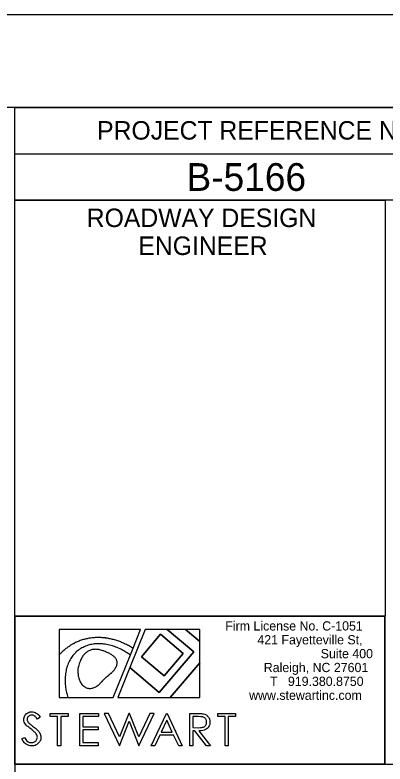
# Model space of a CAD drawing. Extents: x 1967100 to 1968800, y 964086 to 965186.
# Drawn here: x 1968574.5 to 1968674.5, y 964983.4 to 965186 of the extents above; entities that cross this region are included whole.
import ezdxf

# ---------------------------------------------------------------- set-up
doc = ezdxf.new("R2010")
doc.units = 0
for name, color, linetype in [('Sheet Data Field CELL', 7, 'Continuous'), ('Sheet Plan And Profile CELL', 7, 'Continuous'), ('Sheet Sticker Exception Certification CELL', 7, 'Continuous'), ('Stewart Logo', 7, 'Continuous'), ('Stewart Plot Border Xerox6279 and LJ5000', 7, 'Continuous')]:
    doc.layers.add(name, color=color, linetype=linetype)

msp = doc.modelspace()

# ---------------------------------------------------------------- linework, layer by layer
at = {"layer": 'Sheet Plan And Profile CELL'}
msp.add_line((1968574.47, 965148.43), (1968774.52, 965148.43), dxfattribs=at)
for points in [[(1968774.52, 965160.98), (1967274.52, 965160.98), (1967274.52, 964110.98), (1968774.52, 964110.98)], [(1968574.47, 965160.98), (1968774.52, 965160.98), (1968774.52, 965135.93), (1968574.47, 965135.93)], [(1968574.47, 965135.93), (1968674.52, 965135.93), (1968674.52, 965023.43), (1968574.47, 965023.43)], [(1968574.47, 965023.43), (1968674.47, 965023.43), (1968674.47, 964983.43), (1968574.47, 964983.43)]]:
    msp.add_lwpolyline(points, close=True, dxfattribs=at)
at = {"layer": 'Sheet Sticker Exception Certification CELL'}
for p, q in [((1968574.48, 964959.93), (1968574.48, 964983.43)), ((1968574.48, 964983.43), (1968774.52, 964983.43))]:
    msp.add_line(p, q, dxfattribs=at)
at = {"layer": 'Stewart Logo'}
for p, q in [((1968608.44, 965019.83), (1968586.37, 965019.83)), ((1968586.37, 965019.83), (1968586.37, 965012.88)), ((1968609.67, 965019.83), (1968605.52, 965009.51)), ((1968606.39, 965014.72), (1968608.44, 965019.83)), ((1968615.62, 965019.83), (1968609.67, 965019.83)), ((1968615.62, 965019.83), (1968622.77, 965013.74)), ((1968620.52, 965019.83), (1968615.62, 965019.83)), ((1968622.77, 965013.74), (1968615.62, 965019.83)), ((1968624.4, 965019.83), (1968620.52, 965019.83)), ((1968620.52, 965019.83), (1968624.4, 965016.52)), ((1968624.4, 965016.52), (1968620.52, 965019.83)), ((1968624.4, 965016.52), (1968624.4, 965019.83)), ((1968591.31, 965016.49), (1968591.29, 965016.46)), ((1968592.38, 965016.89), (1968592.33, 965016.88)), ((1968598.89, 965017.5), (1968598.9, 965017.5)), ((1968624.4, 965010.75), (1968624.4, 965016.52)), ((1968598.8, 965015.8), (1968598.84, 965015.82)), ((1968604.37, 965015.84), (1968604.38, 965015.84)), ((1968605.66, 965012.91), (1968606.39, 965014.72)), ((1968586.37, 965012.88), (1968586.37, 965001.42)), ((1968601.04, 965001.42), (1968605.66, 965012.91)), ((1968622.77, 965013.74), (1968613.44, 965002.77)), ((1968613.44, 965002.77), (1968622.77, 965013.74)), ((1968614.76, 965007.23), (1968619.94, 965013.32)), ((1968624.4, 965010.75), (1968616.46, 965001.42)), ((1968616.46, 965001.42), (1968624.4, 965010.75)), ((1968624.4, 965001.42), (1968624.4, 965010.75)), ((1968605.52, 965009.51), (1968602.27, 965001.42)), ((1968613.44, 965002.77), (1968605.52, 965009.51)), ((1968605.52, 965009.51), (1968613.44, 965002.77)), ((1968586.37, 965001.42), (1968588.74, 965001.42)), ((1968588.74, 965001.42), (1968601.04, 965001.42)), ((1968602.27, 965001.42), (1968616.46, 965001.42)), ((1968616.46, 965001.42), (1968624.4, 965001.42)), ((1968599.78, 964997.1), (1968598.59, 964997.1)), ((1968598.59, 964997.1), (1968602.71, 964988.35)), ((1968602.76, 964990.79), (1968599.78, 964997.1)), ((1968605.28, 964997.1), (1968602.76, 964990.79)), ((1968605.45, 964997.1), (1968605.28, 964997.1)), ((1968607.93, 964990.79), (1968605.45, 964997.1)), ((1968610.91, 964997.1), (1968607.93, 964990.79)), ((1968607.97, 964988.35), (1968612.1, 964997.1)), ((1968612.1, 964997.1), (1968610.91, 964997.1)), ((1968602.71, 964988.35), (1968605.36, 964994.97)), ((1968605.36, 964994.97), (1968607.97, 964988.35))]:
    msp.add_line(p, q, dxfattribs=at)
msp.add_lwpolyline([(1968674.47, 965023.43), (1968574.47, 965023.43), (1968574.47, 964983.43), (1968674.47, 964983.43)], close=True, dxfattribs=at)
for points in [[(1968608.65, 965012.44), (1968613.83, 965018.53), (1968619.94, 965013.32), (1968614.76, 965007.23), (1968608.65, 965012.44)], [(1968619.94, 965013.32), (1968613.83, 965018.53), (1968608.65, 965012.44), (1968614.76, 965007.23)], [(1968590.35, 965016.02), (1968590.43, 965016.06)], [(1968600.47, 965015.46), (1968600.43, 965015.44)], [(1968587.07, 965013.6), (1968587.01, 965013.56)], [(1968600.04, 965007.65), (1968599.92, 965007.55)], [(1968600.22, 965007.79), (1968600.14, 965007.73)], [(1968600.35, 965007.87), (1968600.28, 965007.84)], [(1968597.84, 965005.61), (1968597.74, 965005.51)], [(1968584.02, 964996.24), (1968584.02, 964997.1), (1968588.81, 964997.1), (1968588.81, 964996.24), (1968586.86, 964996.24), (1968586.86, 964988.35), (1968585.97, 964988.35), (1968585.97, 964996.24), (1968584.02, 964996.24)], [(1968591.98, 964997.1), (1968597, 964997.1), (1968597, 964996.24), (1968592.85, 964996.24), (1968592.85, 964993.5), (1968596.96, 964993.5), (1968596.96, 964992.64), (1968592.85, 964992.64), (1968592.85, 964989.2), (1968596.96, 964989.2), (1968596.96, 964988.35), (1968591.98, 964988.35), (1968591.98, 964997.1)], [(1968615.6, 964997.1), (1968619.68, 964988.35), (1968618.74, 964988.35), (1968617.36, 964991.23), (1968613.59, 964991.23), (1968612.23, 964988.35), (1968611.26, 964988.35), (1968615.39, 964997.1), (1968615.6, 964997.1)], [(1968621.7, 964997.1), (1968623.44, 964997.1)], [(1968624.14, 964992.41), (1968627.29, 964988.35), (1968626.2, 964988.35), (1968623.06, 964992.41), (1968622.57, 964992.41), (1968622.57, 964988.35), (1968621.7, 964988.35), (1968621.7, 964997.1)], [(1968622.57, 964996.24), (1968622.57, 964993.26), (1968624.07, 964993.25)], [(1968624.11, 964996.24), (1968622.57, 964996.24)], [(1968629.29, 964996.24), (1968629.29, 964997.1), (1968634.08, 964997.1), (1968634.08, 964996.24), (1968632.13, 964996.24), (1968632.13, 964988.35), (1968631.24, 964988.35), (1968631.24, 964996.24), (1968629.29, 964996.24)], [(1968581.3, 964996.1), (1968580.59, 964995.56)], [(1968615.49, 964995.24), (1968613.99, 964992.07), (1968616.98, 964992.07), (1968615.49, 964995.24)], [(1968576.33, 964990.2), (1968577.08, 964990.64)]]:
    msp.add_lwpolyline(points, dxfattribs=at)
for centre, radius, start, end in [((1968596.86, 965003.51), 14.11, 108.6948, 113.1331), ((1968596.86, 965003.51), 14.11, 108.6948, 113.1331), ((1968596.71, 965004.08), 13.53, 104.178, 108.6948), ((1968596.71, 965004.08), 13.53, 104.178, 108.6948), ((1968596.86, 965003.51), 14.11, 99.7438, 104.178), ((1968596.86, 965003.51), 14.11, 99.7438, 104.178), ((1968596.89, 965003.32), 14.3, 95.339, 99.7438), ((1968596.89, 965003.32), 14.3, 95.339, 99.7438), ((1968596.91, 965003.06), 14.57, 91.0141, 95.339), ((1968596.91, 965003.06), 14.57, 91.0141, 95.339), ((1968596.93, 965002.18), 15.45, 86.8145, 91.0141), ((1968596.93, 965002.18), 15.45, 86.8145, 91.0141), ((1968596.93, 965002.18), 15.45, 82.6822, 86.8145), ((1968596.93, 965002.18), 15.45, 82.6822, 86.8145), ((1968596.73, 965000.71), 16.93, 78.75, 82.6822), ((1968596.73, 965000.71), 16.93, 78.75, 82.6822), ((1968596.85, 965001.28), 16.35, 74.8634, 78.75), ((1968596.85, 965001.28), 16.35, 74.8634, 78.75), ((1968596.24, 964999.03), 18.68, 71.2279, 74.8634), ((1968596.24, 964999.03), 18.68, 71.2279, 74.8634), ((1968596.61, 965000.12), 17.52, 67.6108, 71.2279), ((1968596.61, 965000.12), 17.52, 67.6108, 71.2279), ((1968597.5, 965002.96), 14.9, 126.3831, 130.5125), ((1968597.5, 965002.96), 14.9, 126.3831, 130.5125), ((1968596.44, 965004.4), 13.11, 121.981, 126.3831), ((1968596.44, 965004.4), 13.11, 121.981, 126.3831), ((1968597.05, 965003.42), 14.27, 117.649, 121.981), ((1968597.05, 965003.42), 14.27, 117.649, 121.981), ((1968596.44, 965004.4), 13.11, 113.1331, 117.649), ((1968596.44, 965004.4), 13.11, 113.1331, 117.649), ((1968596.43, 965007.85), 7.98, 124.1721, 134.1821), ((1968596.43, 965007.85), 7.98, 124.1721, 134.1821), ((1968596.48, 965007.78), 8.06, 114.2575, 124.1721), ((1968596.48, 965007.78), 8.06, 114.2575, 124.1721), ((1968596.96, 965006.72), 9.23, 104.9898, 114.2575), ((1968596.96, 965006.72), 9.23, 104.9898, 114.2575), ((1968596.81, 965007.28), 8.65, 95.9703, 104.9898), ((1968596.81, 965007.28), 8.65, 95.9703, 104.9898), ((1968596.19, 965009.95), 4.49, 91.5398, 97.9017), ((1968596.19, 965009.95), 4.49, 91.5398, 97.9017), ((1968597.15, 965003.99), 11.96, 88.2991, 95.9703), ((1968597.15, 965003.99), 11.96, 88.2991, 95.9703), ((1968596.19, 965009.6), 4.84, 85.6825, 91.5398), ((1968596.19, 965009.6), 4.84, 85.6825, 91.5398), ((1968597.2, 965005.74), 10.21, 80.7637, 88.2991), ((1968597.2, 965005.74), 10.21, 80.7637, 88.2991), ((1968596.27, 965000.21), 15.79, 74.7103, 80.7637), ((1968596.27, 965000.21), 15.79, 74.7103, 80.7637), ((1968597.26, 965003.7), 12.19, 68.5824, 74.7103), ((1968597.26, 965003.7), 12.19, 68.5824, 74.7103), ((1968594.41, 964996.44), 19.99, 63.7978, 68.5824), ((1968594.41, 964996.44), 19.99, 63.7978, 68.5824), ((1968595.44, 964997.28), 20.6, 64.2747, 67.6108), ((1968595.44, 964997.28), 20.6, 64.2747, 67.6108), ((1968595.79, 964998.03), 19.77, 60.9284, 64.2747), ((1968595.79, 964998.03), 19.77, 60.9284, 64.2747), ((1968595.79, 964998.03), 19.77, 57.5922, 60.9284), ((1968595.79, 964998.03), 19.77, 57.5922, 60.9284), ((1968597.05, 965003.42), 14.27, 134.7069, 138.485), ((1968597.05, 965003.42), 14.27, 134.7069, 138.485), ((1968596.84, 965003.74), 13.88, 130.5125, 134.7069), ((1968596.84, 965003.74), 13.88, 130.5125, 134.7069), ((1968596.48, 965007.64), 8.16, 143.7045, 153.1024), ((1968596.48, 965007.64), 8.16, 143.7045, 153.1024), ((1968597.02, 965007.25), 8.82, 134.1821, 143.7045), ((1968597.02, 965007.25), 8.82, 134.1821, 143.7045), ((1968597.56, 965009.32), 5.77, 144.895, 150.0914), ((1968597.56, 965009.32), 5.77, 144.895, 150.0914), ((1968597.15, 965009.61), 5.27, 139.1543, 144.895), ((1968597.15, 965009.61), 5.27, 139.1543, 144.895), ((1968596.47, 965010.2), 4.37, 132.8496, 139.1543), ((1968596.47, 965010.2), 4.37, 132.8496, 139.1543), ((1968596.28, 965010.4), 4.1, 126.1002, 132.8496), ((1968596.28, 965010.4), 4.1, 126.1002, 132.8496), ((1968596.06, 965010.7), 3.73, 119.026, 126.1002), ((1968596.06, 965010.7), 3.73, 119.026, 126.1002), ((1968596.03, 965010.76), 3.66, 111.8278, 119.026), ((1968596.03, 965010.76), 3.66, 111.8278, 119.026), ((1968596.07, 965010.66), 3.77, 104.7285, 111.8278), ((1968596.07, 965010.66), 3.77, 104.7285, 111.8278), ((1968596.1, 965010.53), 3.9, 97.9017, 104.7285), ((1968596.1, 965010.53), 3.9, 97.9017, 104.7285), ((1968596.11, 965008.43), 6.01, 80.427, 85.6825), ((1968596.11, 965008.43), 6.01, 80.427, 85.6825), ((1968596.01, 965007.86), 6.59, 75.6971, 80.427), ((1968596.01, 965007.86), 6.59, 75.6971, 80.427), ((1968595.54, 965006.03), 8.48, 71.5292, 75.6971), ((1968595.54, 965006.03), 8.48, 71.5292, 75.6971), ((1968594.9, 965004.1), 10.52, 67.7999, 71.5292), ((1968594.9, 965004.1), 10.52, 67.7999, 71.5292), ((1968595.69, 965006.04), 8.42, 63.632, 67.7999), ((1968595.69, 965006.04), 8.42, 63.632, 67.7999), ((1968596.93, 965007.47), 6.6, 63.9022, 67.7899), ((1968596.93, 965007.47), 6.6, 63.9022, 67.7899), ((1968596.03, 965005.62), 8.66, 60.5091, 63.9022), ((1968596.03, 965005.62), 8.66, 60.5091, 63.9022), ((1968597.01, 965007.36), 6.66, 56.6214, 60.5091), ((1968597.01, 965007.36), 6.66, 56.6214, 60.5091), ((1968597.99, 965008.85), 4.87, 52.0757, 56.6214), ((1968597.99, 965008.85), 4.87, 52.0757, 56.6214), ((1968598.35, 965009.31), 4.29, 46.8444, 52.0757), ((1968598.35, 965009.31), 4.29, 46.8444, 52.0757), ((1968599.11, 965010.12), 3.19, 40.7768, 46.8444), ((1968599.11, 965010.12), 3.19, 40.7768, 46.8444), ((1968596.27, 965000.21), 15.79, 58.7784, 63.7978), ((1968596.27, 965000.21), 15.79, 58.7784, 63.7978), ((1968595.44, 964998.85), 17.37, 53.9938, 58.7784), ((1968595.44, 964998.85), 17.37, 53.9938, 58.7784), ((1968599.08, 965006.33), 11.07, 153.1024, 161.1689), ((1968599.08, 965006.33), 11.07, 153.1024, 161.1689), ((1968604.18, 965006.61), 12.95, 162.4501, 165.6937), ((1968604.18, 965006.61), 12.95, 162.4501, 165.6937), ((1968601.81, 965007.36), 10.47, 158.8258, 162.4501), ((1968601.81, 965007.36), 10.47, 158.8258, 162.4501), ((1968599.59, 965008.22), 8.09, 154.7022, 158.8258), ((1968599.59, 965008.22), 8.09, 154.7022, 158.8258), ((1968598.91, 965008.55), 7.33, 150.0914, 154.7022), ((1968598.91, 965008.55), 7.33, 150.0914, 154.7022), ((1968599.38, 965010.35), 2.84, 33.8961, 40.7768), ((1968599.38, 965010.35), 2.84, 33.8961, 40.7768), ((1968599.85, 965010.67), 2.26, 26.1882, 33.8961), ((1968599.85, 965010.67), 2.26, 26.1882, 33.8961), ((1968600, 965010.74), 2.1, 17.8594, 26.1882), ((1968600, 965010.74), 2.1, 17.8594, 26.1882), ((1968600.16, 965010.79), 1.93, 9.1711, 17.8594), ((1968600.16, 965010.79), 1.93, 9.1711, 17.8594), ((1968599.79, 965010.81), 2.3, 344.6304, 352.2444), ((1968599.79, 965010.81), 2.3, 344.6304, 352.2444), ((1968600.15, 965010.79), 1.93, 0.507, 9.1711), ((1968600.15, 965010.79), 1.93, 0.507, 9.1711), ((1968599.96, 965010.79), 2.13, 352.2444, 0.507), ((1968599.96, 965010.79), 2.13, 352.2444, 0.507), ((1968602.55, 965005.89), 14.55, 169.1279, 175.5255), ((1968602.55, 965005.89), 14.55, 169.1279, 175.5255), ((1968597.5, 965006.86), 9.4, 161.1689, 169.1279), ((1968597.5, 965006.86), 9.4, 161.1689, 169.1279), ((1968599.05, 965008.51), 7.59, 174.9583, 179.1125), ((1968599.05, 965008.51), 7.59, 174.9583, 179.1125), ((1968598.24, 965008.52), 6.78, 179.1125, 183.5072), ((1968598.24, 965008.52), 6.78, 179.1125, 183.5072), ((1968601.68, 965007.25), 10.38, 165.6937, 169.3181), ((1968601.68, 965007.25), 10.38, 165.6937, 169.3181), ((1968594.37, 965014.46), 8.89, 315.1414, 318.4744), ((1968594.37, 965014.46), 8.89, 315.1414, 318.4744), ((1968595.91, 965013.1), 6.85, 318.4744, 322.2915), ((1968595.91, 965013.1), 6.85, 318.4744, 322.2915), ((1968597.36, 965011.98), 5.01, 322.2915, 326.7539), ((1968597.36, 965011.98), 5.01, 322.2915, 326.7539), ((1968597.86, 965011.65), 4.41, 326.7539, 331.8907), ((1968597.86, 965011.65), 4.41, 326.7539, 331.8907), ((1968598.87, 965011.11), 3.27, 331.8907, 337.8545), ((1968598.87, 965011.11), 3.27, 331.8907, 337.8545), ((1968599.21, 965010.97), 2.9, 337.8545, 344.6304), ((1968599.21, 965010.97), 2.9, 337.8545, 344.6304), ((1968599.26, 965006.15), 11.25, 175.5255, 181.9873), ((1968599.26, 965006.15), 11.25, 175.5255, 181.9873), ((1968600.21, 965008.64), 8.75, 183.5072, 187.6613), ((1968600.21, 965008.64), 8.75, 183.5072, 187.6613), ((1968596.87, 965008.19), 5.39, 187.6614, 192.9555), ((1968596.87, 965008.19), 5.39, 187.6614, 192.9555), ((1968598.44, 965008.55), 6.99, 192.9555, 198.184), ((1968598.44, 965008.55), 6.99, 192.9555, 198.184), ((1968596.02, 965007.76), 4.45, 198.184, 204.7361), ((1968596.02, 965007.76), 4.45, 198.184, 204.7361), ((1968630.94, 964972.47), 46.84, 133.5368, 133.8764), ((1968630.94, 964972.47), 46.84, 133.5368, 133.8764), ((1968625.78, 964977.9), 39.35, 133.1663, 133.5368), ((1968625.78, 964977.9), 39.35, 133.1663, 133.5368), ((1968628.55, 964974.95), 43.39, 132.7975, 133.1663), ((1968628.55, 964974.95), 43.39, 132.7975, 133.1663), ((1968623.72, 964980.17), 36.29, 132.3943, 132.7975), ((1968623.72, 964980.17), 36.29, 132.3943, 132.7975), ((1968621.54, 964982.56), 33.05, 131.9515, 132.3943), ((1968621.54, 964982.56), 33.05, 131.9515, 132.3943), ((1968617.61, 964986.93), 27.17, 131.4632, 131.9515), ((1968617.61, 964986.93), 27.17, 131.4632, 131.9515), ((1968613, 964992.15), 20.21, 130.8651, 131.4632), ((1968613, 964992.15), 20.21, 130.8651, 131.4632), ((1968610.12, 964995.48), 15.81, 130.1887, 130.8651), ((1968610.12, 964995.48), 15.81, 130.1887, 130.8651), ((1968606.06, 965000.28), 9.52, 129.2494, 130.1887), ((1968604.22, 965002.53), 6.61, 128.1219, 129.2494), ((1968604.22, 965002.53), 6.61, 128.1219, 129.2494), ((1968602.08, 965005.26), 3.14, 126.2742, 128.1219), ((1968601.19, 965006.47), 1.64, 123.718, 126.2741), ((1968601.19, 965006.47), 1.64, 123.718, 126.2741), ((1968600.42, 965007.63), 0.249, 118.0607, 123.718), ((1968600.88, 965006.77), 1.22, 115.5046, 118.0608), ((1968595.87, 965012.97), 6.78, 311.3243, 315.1414), ((1968595.87, 965012.97), 6.78, 311.3243, 315.1414), ((1968606.61, 965006.41), 18.6, 181.9873, 187.0116), ((1968606.61, 965006.41), 18.6, 181.9873, 187.0116), ((1968596.65, 965008.05), 5.14, 204.7361, 211.5103), ((1968596.65, 965008.05), 5.14, 204.7361, 211.5103), ((1968595.27, 965007.21), 3.53, 211.5103, 219.6861), ((1968595.27, 965007.21), 3.53, 211.5103, 219.6861), ((1968595.35, 965007.26), 3.62, 219.6861, 228.4088), ((1968595.35, 965007.26), 3.62, 219.6861, 228.4088), ((1968594.86, 965006.71), 2.88, 228.4088, 238.184), ((1968594.86, 965006.71), 2.88, 228.4088, 238.184), ((1968594.72, 965007.15), 3.28, 295.379, 302.7203), ((1968594.72, 965007.15), 3.28, 295.379, 302.7203), ((1968593.45, 965009.12), 5.62, 302.7203, 308.3257), ((1968593.45, 965009.12), 5.62, 302.7203, 308.3257), ((1968594.03, 965008.39), 4.68, 308.3257, 314.0568), ((1968594.03, 965008.39), 4.68, 308.3257, 314.0568), ((1968593.88, 965008.54), 4.9, 314.0568, 319.6622), ((1968593.88, 965008.54), 4.9, 314.0568, 319.6622), ((1968617.67, 964986.15), 27.78, 135.8419, 136.2162), ((1968617.67, 964986.15), 27.78, 135.8419, 136.2162), ((1968610.27, 964993.34), 17.46, 135.3698, 135.8419), ((1968621.06, 964982.69), 32.63, 134.9955, 135.3698), ((1968621.06, 964982.69), 32.63, 134.9955, 135.3698), ((1968617.74, 964986.01), 27.93, 134.5909, 134.9955), ((1968617.74, 964986.01), 27.93, 134.5909, 134.9955), ((1968627.86, 964975.74), 42.35, 134.2487, 134.5909), ((1968627.86, 964975.74), 42.35, 134.2487, 134.5909), ((1968623.26, 964980.46), 35.75, 133.8764, 134.2487), ((1968623.26, 964980.46), 35.75, 133.8764, 134.2487), ((1968602.9, 965005.95), 14.86, 187.0116, 192.2545), ((1968602.9, 965005.95), 14.86, 187.0116, 192.2545), ((1968604.19, 965006.23), 16.17, 192.2545, 197.2789), ((1968604.19, 965006.23), 16.17, 192.2545, 197.2789), ((1968594.76, 965006.56), 2.71, 238.184, 248.5685), ((1968594.76, 965006.56), 2.71, 238.184, 248.5685), ((1968594.77, 965006.58), 2.73, 248.5685, 258.9188), ((1968594.77, 965006.58), 2.73, 248.5685, 258.9188), ((1968594.71, 965006.29), 2.43, 258.9188, 269.5093), ((1968594.71, 965006.29), 2.43, 258.9188, 269.5093), ((1968594.72, 965007.02), 3.16, 269.5093, 278.793), ((1968594.72, 965007.02), 3.16, 269.5093, 278.793), ((1968594.8, 965006.54), 2.67, 278.793, 288.0103), ((1968594.8, 965006.54), 2.67, 278.793, 288.0103), ((1968594.33, 965007.97), 4.18, 288.0103, 295.379), ((1968594.33, 965007.97), 4.18, 288.0103, 295.379)]:
    msp.add_arc(centre, radius, start, end, dxfattribs=at)
for points in [[(1968580.59, 964995.56), (1968580.09, 964996.21), (1968579.74, 964996.42), (1968579.4, 964996.63), (1968578.99, 964996.63), (1968578.46, 964996.63), (1968578.12, 964996.31), (1968577.78, 964995.99), (1968577.78, 964995.52), (1968577.78, 964995.23), (1968577.9, 964994.96), (1968578.02, 964994.7), (1968578.34, 964994.38), (1968578.51, 964994.21), (1968579.47, 964993.51), (1968580.6, 964992.67), (1968581.03, 964992.01), (1968581.45, 964991.36), (1968581.45, 964990.7), (1968581.45, 964989.75), (1968580.73, 964989.05), (1968580, 964988.35), (1968578.97, 964988.35), (1968578.17, 964988.35), (1968577.53, 964988.77), (1968576.88, 964989.2), (1968576.33, 964990.2)], [(1968577.08, 964990.64), (1968577.86, 964989.2), (1968578.89, 964989.2), (1968579.33, 964989.2), (1968579.72, 964989.4), (1968580.1, 964989.61), (1968580.3, 964989.95), (1968580.51, 964990.3), (1968580.51, 964990.68), (1968580.51, 964991.12), (1968580.21, 964991.54), (1968579.8, 964992.13), (1968578.71, 964992.95), (1968577.62, 964993.77), (1968577.35, 964994.14), (1968576.89, 964994.76), (1968576.89, 964995.48), (1968576.89, 964996.05), (1968577.16, 964996.52), (1968577.43, 964996.99), (1968577.93, 964997.26), (1968578.42, 964997.54), (1968579.01, 964997.54), (1968579.62, 964997.54), (1968580.16, 964997.23), (1968580.7, 964996.92), (1968581.3, 964996.1)], [(1968623.44, 964997.1), (1968624.89, 964997.1), (1968625.41, 964996.98), (1968626.18, 964996.8), (1968626.67, 964996.21), (1968627.16, 964995.62), (1968627.16, 964994.77), (1968627.16, 964994.05), (1968626.82, 964993.51), (1968626.49, 964992.97), (1968625.86, 964992.69), (1968625.24, 964992.41), (1968624.14, 964992.41)], [(1968624.07, 964993.25), (1968624.95, 964993.25), (1968625.37, 964993.42), (1968625.79, 964993.58), (1968626.02, 964993.95), (1968626.26, 964994.32), (1968626.26, 964994.77), (1968626.26, 964995.21), (1968626.02, 964995.57), (1968625.78, 964995.93), (1968625.39, 964996.08), (1968625.01, 964996.24), (1968624.11, 964996.24)]]:
    msp.add_open_spline(points, degree=3, dxfattribs=at)
at = {"layer": 'Stewart Plot Border Xerox6279 and LJ5000'}
msp.add_lwpolyline([(1967099.52, 964085.98), (1968799.52, 964085.98), (1968799.52, 965185.98), (1967099.52, 965185.98)], close=True, dxfattribs=at)

# ---------------------------------------------------------------- texts
at = {"layer": 'Sheet Data Field CELL'}
msp.add_text('B-5166', height=7.5, rotation=360, dxfattribs=at).set_placement((1968620.82, 965138.41))
at = {"layer": 'Sheet Plan And Profile CELL'}
for s, height, p in [('PROJECT REFERENCE NO.', 5.0001, (1968596.67, 965152.28)), ('ROADWAY DESIGN', 5.0001, (1968593.87, 965128.63)), ('ENGINEER', 5, (1968607.82, 965121.08))]:
    msp.add_text(s, height=height, rotation=360, dxfattribs=at).set_placement(p)
at = {"layer": 'Stewart Logo'}
for s, p in [('Firm License No. C-1051', (1968631.32, 965019.53)), ('421 Fayetteville St,', (1968639.99, 965015.78)), ('Suite 400', (1968657.11, 965012.03)), ('Raleigh, NC 27601', (1968641.72, 965008.28)), ('T   919.380.8750', (1968643.42, 965004.53)), ('www.stewartinc.com', (1968637.76, 965000.78))]:
    msp.add_text(s, height=2.5, rotation=0, dxfattribs=at).set_placement(p)

doc.saveas('drawing.dxf')
